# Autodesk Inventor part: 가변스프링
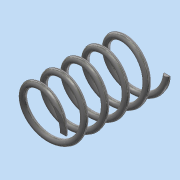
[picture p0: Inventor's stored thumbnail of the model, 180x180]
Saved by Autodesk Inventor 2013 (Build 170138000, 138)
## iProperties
Created: 2017-02
Part Number: 가변스프링
Material: 강철, 탄소
Document SubType Name: Modeling
Designer: dgall
Density: 7.87 g/cm^3
Mass: 6.52211 g
Surface Area: 16.8018 cm^2
Volume: 0.82873 cm^3
Author: dgall
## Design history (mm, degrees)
sketch "스케치1"
  geometry: L1 (0, 0)-(0, 35); L2 (0, 0)-(8.5, 0); L3 (0, 35)-(8.5, 35); C1 r 1 at (8.5, 0)
  constraints: 6 end point, 1 centre point, 1 coincident, 1 parallel, 1 perpendicular, 1 vertical, 1 vertical alignment
  dimensions: "d0" = 35 distance of L1.start L1.end (derived); "d1" = 2 diameter of C1; "d2" = 17 diameter of L2.end L1
feature "코일1" sketch "스케치1" pitch "d3" = 10; turns "d5" = 5; dims "d4" = 35 (= d0), "d6" = 0, angle "d7" = 90 deg, angle "d8" = 90 deg, "d9" = 0, "d10" = 0
node "작업 평면1"
node "작업 평면2"
feature "분할1"
feature "분할2"
node "솔리드1"
other parameters: "d11" = 0, "d12" = 0
